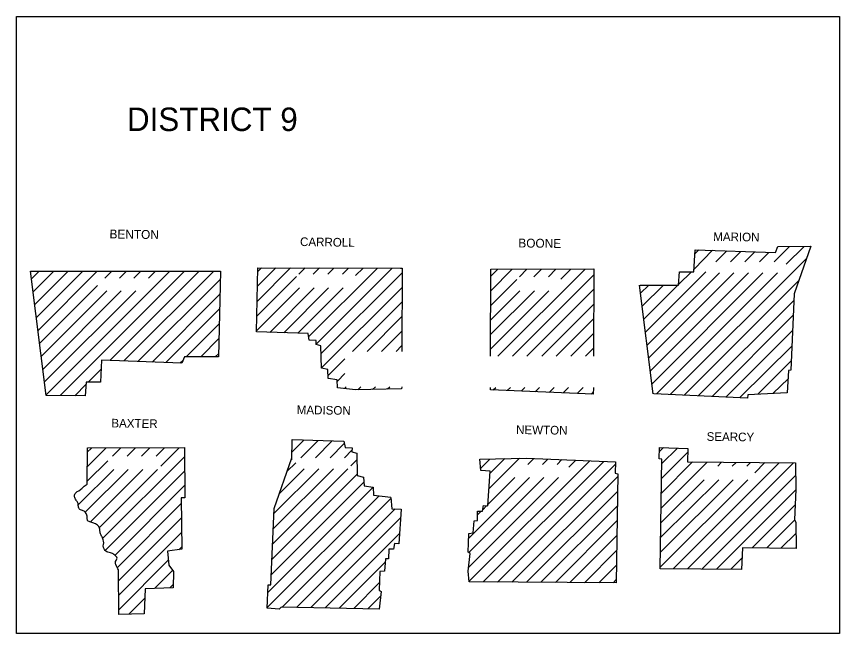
# Model space of a CAD drawing. Extents: x 21307 to 29830, y 1322443 to 1332359.
# Drawn here: x 27385.4 to 27785.4, y 1325389.9 to 1325689.9 of the extents above; entities that cross this region are included whole.
import ezdxf

# ---------------------------------------------------------------- set-up
doc = ezdxf.new("R2010")
doc.units = 0
doc.layers.add('R_Draft', color=7, linetype='Continuous')

msp = doc.modelspace()

# ---------------------------------------------------------------- linework, layer by layer
at = {"layer": 'R_Draft'}
msp.add_lwpolyline([(27385.36, 1325389.92), (27385.36, 1325689.92), (27785.36, 1325689.92), (27785.36, 1325389.92)], close=True, dxfattribs=at)
for points in [[(27688.46, 1325559.32), (27707.16, 1325559.22), (27707.66, 1325565.82), (27714.56, 1325565.82), (27715.16, 1325576.52), (27754.16, 1325575.12), (27755.36, 1325578.12), (27771.46, 1325578.22), (27763.36, 1325555.02), (27761.76, 1325517.92), (27760.56, 1325517.82), (27759.96, 1325506.92)], [(27714.66, 1325567.12), (27723.66, 1325576.22)], [(27715.06, 1325574.52), (27716.96, 1325576.42)], [(27753.56, 1325570.62), (27761.06, 1325578.12)], [(27759.46, 1325569.52), (27768.16, 1325578.12)], [(27703.16, 1325506.22), (27769.36, 1325572.32)], [(27725.26, 1325570.62), (27730.56, 1325575.92)], [(27732.36, 1325570.62), (27737.36, 1325575.72)], [(27739.36, 1325570.62), (27744.26, 1325575.52)], [(27746.46, 1325570.62), (27750.96, 1325575.22)], [(27399.76, 1325505.62), (27392.16, 1325566.12)], [(27392.16, 1325566.12), (27484.46, 1325566.12)], [(27392.66, 1325562.42), (27396.46, 1325566.12)], [(27393.46, 1325556.12), (27403.46, 1325566.12)], [(27394.26, 1325549.92), (27410.46, 1325566.12)], [(27395.06, 1325543.62), (27417.56, 1325566.12)], [(27395.86, 1325537.32), (27424.66, 1325566.12)], [(27399.86, 1325505.92), (27459.96, 1325566.12)], [(27406.66, 1325505.62), (27467.06, 1325566.12)], [(27428.26, 1325562.62), (27431.76, 1325566.12)], [(27430.76, 1325522.62), (27474.16, 1325566.12)], [(27435.36, 1325562.62), (27438.76, 1325566.12)], [(27437.56, 1325522.42), (27481.26, 1325566.12)], [(27442.36, 1325562.62), (27445.86, 1325566.12)], [(27449.46, 1325562.62), (27452.96, 1325566.12)], [(27484.46, 1325566.12), (27483.56, 1325524.52)], [(27501.96, 1325536.52), (27502.66, 1325567.72)], [(27502.26, 1325551.42), (27518.56, 1325567.72)], [(27502.46, 1325558.72), (27511.46, 1325567.72)], [(27502.66, 1325565.92), (27504.46, 1325567.72)], [(27502.66, 1325567.72), (27572.06, 1325567.62), (27572.76, 1325567.62)], [(27522.56, 1325564.62), (27525.66, 1325567.72)], [(27527.36, 1325534.12), (27560.86, 1325567.62)], [(27529.56, 1325564.62), (27532.66, 1325567.72)], [(27530.96, 1325530.62), (27567.96, 1325567.62)], [(27533.46, 1325526.02), (27572.76, 1325565.32)], [(27536.76, 1325564.62), (27539.66, 1325567.62)], [(27543.76, 1325564.62), (27546.76, 1325567.62)], [(27550.16, 1325563.92), (27553.86, 1325567.62)], [(27572.76, 1325567.62), (27572.66, 1325527.02)], [(27615.76, 1325563.52), (27619.26, 1325567.02)], [(27615.76, 1325524.72), (27615.86, 1325567.02)], [(27615.86, 1325567.02), (27665.96, 1325567.22)], [(27615.86, 1325556.52), (27626.26, 1325567.02)], [(27619.36, 1325524.72), (27661.76, 1325567.12)], [(27626.46, 1325524.72), (27665.86, 1325564.12)], [(27629.76, 1325563.32), (27633.46, 1325567.02)], [(27636.76, 1325563.32), (27640.46, 1325567.02)], [(27643.86, 1325563.32), (27647.56, 1325567.02)], [(27649.86, 1325562.22), (27654.76, 1325567.12)], [(27665.96, 1325567.22), (27665.76, 1325524.72)], [(27691.06, 1325536.42), (27720.36, 1325565.72)], [(27691.86, 1325530.12), (27726.96, 1325565.22)], [(27692.66, 1325523.92), (27733.96, 1325565.22)], [(27693.46, 1325517.62), (27741.06, 1325565.22)], [(27694.26, 1325511.32), (27748.16, 1325565.22)], [(27696.46, 1325506.52), (27755.26, 1325565.22)], [(27707.26, 1325559.72), (27713.36, 1325565.82)], [(27444.36, 1325522.22), (27484.36, 1325562.12)], [(27502.16, 1325544.22), (27521.46, 1325563.52)], [(27615.86, 1325549.42), (27628.46, 1325562.02)], [(27709.96, 1325505.92), (27765.56, 1325561.52)], [(27396.66, 1325531.02), (27424.76, 1325559.12)], [(27397.46, 1325524.72), (27429.26, 1325556.52)], [(27398.26, 1325518.52), (27436.26, 1325556.52)], [(27399.06, 1325512.22), (27443.36, 1325556.52)], [(27501.96, 1325537.02), (27522.86, 1325557.92)], [(27508.46, 1325536.32), (27530.06, 1325557.92)], [(27515.26, 1325536.12), (27537.06, 1325557.92)], [(27522.16, 1325535.92), (27544.16, 1325557.92)], [(27533.56, 1325519.02), (27572.76, 1325558.22)], [(27615.76, 1325528.12), (27644.16, 1325556.52)], [(27615.76, 1325535.22), (27637.06, 1325556.52)], [(27615.86, 1325542.42), (27629.96, 1325556.52)], [(27633.46, 1325524.72), (27665.86, 1325557.12)], [(27694.76, 1325506.52), (27688.16, 1325559.32)], [(27688.66, 1325555.32), (27692.76, 1325559.32)], [(27689.46, 1325549.02), (27699.76, 1325559.32)], [(27690.26, 1325542.72), (27706.76, 1325559.32)], [(27451.26, 1325521.92), (27484.16, 1325554.92)], [(27716.66, 1325505.52), (27763.26, 1325552.02)], [(27548.66, 1325527.02), (27572.66, 1325551.02)], [(27640.66, 1325524.72), (27665.86, 1325549.92)], [(27457.96, 1325521.62), (27484.06, 1325547.72)], [(27555.76, 1325527.02), (27572.66, 1325544.02)], [(27723.46, 1325505.22), (27762.86, 1325544.62)], [(27467.86, 1325524.42), (27483.86, 1325540.52)], [(27647.66, 1325524.72), (27665.86, 1325542.92)], [(27572.66, 1325509.92), (27572.56, 1325508.92), (27550.16, 1325508.42), (27541.46, 1325509.32), (27541.26, 1325513.32), (27536.86, 1325513.92), (27536.66, 1325518.22), (27533.56, 1325518.92), (27533.36, 1325529.82), (27530.96, 1325530.42), (27531.06, 1325532.42), (27527.66, 1325532.52), (27527.06, 1325535.72), (27501.96, 1325536.52)], [(27562.76, 1325527.02), (27572.56, 1325536.82)], [(27730.26, 1325504.92), (27762.56, 1325537.32)], [(27474.96, 1325524.42), (27483.76, 1325533.32)], [(27654.76, 1325524.72), (27665.76, 1325535.72)], [(27569.86, 1325527.02), (27572.56, 1325529.82)], [(27661.86, 1325524.72), (27665.76, 1325528.62)], [(27736.96, 1325504.62), (27762.26, 1325529.82)], [(27483.56, 1325524.52), (27466.96, 1325524.42), (27465.76, 1325521.42), (27426.76, 1325522.82), (27426.16, 1325512.12), (27419.26, 1325512.12), (27418.76, 1325505.52), (27399.76, 1325505.62)], [(27481.96, 1325524.42), (27483.66, 1325526.02)], [(27464.76, 1325521.42), (27466.46, 1325523.02)], [(27536.86, 1325515.32), (27544.96, 1325523.42)], [(27745.66, 1325506.22), (27761.86, 1325522.42)], [(27420.16, 1325512.12), (27426.56, 1325518.52)], [(27541.36, 1325512.62), (27544.96, 1325516.32)], [(27753.16, 1325506.72), (27760.36, 1325513.82)], [(27413.66, 1325505.52), (27419.26, 1325511.22)], [(27544.76, 1325509.02), (27545.66, 1325509.92)], [(27551.26, 1325508.42), (27552.76, 1325509.92)], [(27558.46, 1325508.52), (27559.86, 1325509.92)], [(27565.76, 1325508.82), (27566.86, 1325509.92)], [(27615.66, 1325508.32), (27615.76, 1325509.52)], [(27665.66, 1325506.22), (27615.66, 1325508.32)], [(27617.06, 1325508.32), (27618.26, 1325509.52)], [(27623.86, 1325508.02), (27625.46, 1325509.52)], [(27630.66, 1325507.72), (27632.46, 1325509.52)], [(27637.46, 1325507.42), (27639.56, 1325509.52)], [(27644.26, 1325507.12), (27646.66, 1325509.52)], [(27651.06, 1325506.92), (27653.66, 1325509.52)], [(27657.86, 1325506.62), (27660.76, 1325509.52)], [(27665.76, 1325509.52), (27665.66, 1325506.22)], [(27664.66, 1325506.32), (27665.76, 1325507.42)], [(27759.96, 1325506.92), (27740.76, 1325506.02), (27740.56, 1325504.42), (27695.06, 1325506.52)], [(27519.16, 1325474.42), (27519.36, 1325484.32)], [(27519.16, 1325478.12), (27525.16, 1325484.12)], [(27519.36, 1325484.32), (27544.46, 1325483.52), (27545.06, 1325480.32), (27548.46, 1325480.22), (27548.36, 1325478.22), (27550.76, 1325477.62), (27550.96, 1325466.72), (27554.06, 1325466.02), (27554.26, 1325461.72), (27558.66, 1325461.12), (27558.86, 1325457.12), (27567.36, 1325456.22)], [(27419.66, 1325462.62), (27419.86, 1325480.22)], [(27419.76, 1325471.02), (27428.86, 1325480.12)], [(27419.76, 1325478.12), (27421.86, 1325480.12)], [(27419.86, 1325480.22), (27466.96, 1325480.32)], [(27432.06, 1325476.22), (27435.96, 1325480.12)], [(27466.96, 1325480.32), (27467.16, 1325455.92), (27465.46, 1325455.82), (27465.76, 1325430.92), (27458.76, 1325429.92), (27459.36, 1325423.22), (27461.76, 1325420.12), (27461.56, 1325412.22), (27447.96, 1325411.72), (27447.46, 1325399.52), (27435.06, 1325399.12)], [(27439.16, 1325476.22), (27443.06, 1325480.12)], [(27446.16, 1325476.22), (27450.16, 1325480.22)], [(27453.26, 1325476.22), (27457.26, 1325480.22)], [(27455.46, 1325471.32), (27464.36, 1325480.22)], [(27523.56, 1325475.42), (27531.96, 1325483.82)], [(27530.66, 1325475.42), (27538.86, 1325483.62)], [(27537.76, 1325475.42), (27544.66, 1325482.32)], [(27698.26, 1325421.42), (27699.06, 1325474.62), (27697.76, 1325474.92), (27697.86, 1325480.42)], [(27697.86, 1325480.42), (27711.56, 1325479.82), (27711.46, 1325473.32), (27763.96, 1325472.92)], [(27697.86, 1325478.42), (27699.76, 1325480.42)], [(27699.06, 1325472.52), (27706.56, 1325480.02)], [(27544.76, 1325475.42), (27548.36, 1325479.02)], [(27698.96, 1325465.42), (27711.46, 1325477.92)], [(27419.76, 1325463.92), (27429.76, 1325473.92)], [(27427.36, 1325436.22), (27466.96, 1325475.82)], [(27561.66, 1325401.82), (27513.96, 1325402.72), (27513.06, 1325401.82), (27507.16, 1325402.32), (27507.76, 1325413.52), (27508.96, 1325413.62), (27510.56, 1325450.72), (27519.16, 1325475.42)], [(27516.76, 1325468.62), (27521.06, 1325472.92)], [(27547.86, 1325471.52), (27550.76, 1325474.42)], [(27604.86, 1325420.32), (27605.86, 1325428.82), (27604.86, 1325429.52), (27605.16, 1325438.52), (27607.36, 1325438.82), (27607.86, 1325444.72), (27609.36, 1325444.82), (27609.46, 1325449.42), (27611.86, 1325449.42), (27612.26, 1325452.12), (27614.36, 1325452.02), (27615.56, 1325468.82), (27610.96, 1325469.12), (27610.56, 1325474.72)], [(27605.36, 1325415.32), (27664.06, 1325473.92)], [(27610.56, 1325474.72), (27610.76, 1325474.72), (27633.16, 1325475.22)], [(27610.96, 1325470.32), (27615.36, 1325474.72)], [(27612.16, 1325415.02), (27670.86, 1325473.62)], [(27614.96, 1325460.22), (27629.86, 1325475.12)], [(27615.46, 1325467.72), (27622.66, 1325475.02)], [(27619.16, 1325414.92), (27676.36, 1325472.12)], [(27633.16, 1325475.22), (27676.46, 1325473.42)], [(27633.96, 1325472.12), (27636.86, 1325475.02)], [(27641.06, 1325472.12), (27643.66, 1325474.72)], [(27648.06, 1325472.12), (27650.46, 1325474.52)], [(27653.86, 1325470.82), (27657.26, 1325474.22)], [(27676.46, 1325473.42), (27676.36, 1325467.92), (27677.66, 1325467.62), (27676.86, 1325414.52)], [(27698.76, 1325451.02), (27720.96, 1325473.22)], [(27698.86, 1325458.22), (27713.96, 1325473.32)], [(27704.46, 1325421.42), (27756.06, 1325472.92)], [(27711.46, 1325421.32), (27763.06, 1325472.92)], [(27726.16, 1325471.32), (27728.06, 1325473.22)], [(27733.26, 1325471.32), (27735.06, 1325473.12)], [(27740.26, 1325471.32), (27742.06, 1325473.12)], [(27744.16, 1325468.12), (27749.06, 1325473.02)], [(27763.96, 1325472.92), (27764.06, 1325460.02)], [(27415.36, 1325452.52), (27432.66, 1325469.72)], [(27418.96, 1325449.02), (27439.66, 1325469.72)], [(27421.16, 1325444.12), (27446.76, 1325469.72)], [(27425.66, 1325441.52), (27453.86, 1325469.72)], [(27428.66, 1325430.42), (27467.06, 1325468.82)], [(27509.86, 1325433.42), (27546.46, 1325470.02)], [(27510.16, 1325440.82), (27539.36, 1325470.02)], [(27510.46, 1325448.22), (27532.36, 1325470.02)], [(27513.06, 1325457.92), (27525.26, 1325470.02)], [(27509.56, 1325426.12), (27550.86, 1325467.42)], [(27605.16, 1325422.12), (27648.76, 1325465.72)], [(27605.16, 1325436.22), (27634.66, 1325465.72)], [(27605.26, 1325429.32), (27641.66, 1325465.72)], [(27614.46, 1325452.62), (27627.56, 1325465.72)], [(27626.16, 1325414.82), (27677.56, 1325466.32)], [(27698.36, 1325422.32), (27740.76, 1325464.72)], [(27698.36, 1325429.42), (27733.66, 1325464.72)], [(27698.56, 1325436.72), (27726.66, 1325464.72)], [(27698.56, 1325443.82), (27719.56, 1325464.72)], [(27718.46, 1325421.22), (27763.96, 1325466.72)], [(27433.26, 1325428.02), (27467.06, 1325461.82)], [(27507.56, 1325409.92), (27558.66, 1325461.02)], [(27509.26, 1325418.62), (27554.16, 1325463.52)], [(27764.06, 1325460.02), (27763.46, 1325445.22), (27764.16, 1325444.02), (27764.36, 1325431.32)], [(27507.26, 1325402.52), (27561.46, 1325456.72)], [(27567.36, 1325456.02), (27567.76, 1325450.62), (27572.36, 1325450.32), (27571.16, 1325433.52), (27569.06, 1325433.62), (27568.66, 1325430.92), (27566.26, 1325430.92), (27566.16, 1325426.32), (27564.66, 1325426.22), (27564.16, 1325420.32), (27561.96, 1325420.02), (27561.66, 1325411.02), (27562.66, 1325410.32), (27561.66, 1325401.82)], [(27633.26, 1325414.82), (27677.56, 1325459.12)], [(27725.56, 1325421.22), (27763.96, 1325459.62)], [(27434.46, 1325422.02), (27465.46, 1325453.12)], [(27514.56, 1325402.72), (27567.36, 1325455.52)], [(27611.96, 1325450.12), (27613.86, 1325452.02)], [(27742.96, 1325431.62), (27763.76, 1325452.42)], [(27521.46, 1325402.62), (27569.36, 1325450.52)], [(27609.46, 1325447.62), (27611.26, 1325449.42)], [(27640.26, 1325414.82), (27677.36, 1325451.92)], [(27434.96, 1325415.52), (27465.56, 1325446.12)], [(27528.46, 1325402.52), (27571.96, 1325446.12)], [(27647.26, 1325414.72), (27677.36, 1325444.82)], [(27749.96, 1325431.52), (27763.56, 1325445.12)], [(27435.06, 1325408.52), (27465.56, 1325439.12)], [(27535.36, 1325402.42), (27571.46, 1325438.52)], [(27654.36, 1325414.72), (27677.16, 1325437.52)], [(27756.86, 1325431.42), (27764.26, 1325438.72)], [(27464.26, 1325430.62), (27465.66, 1325432.12)], [(27661.36, 1325414.62), (27677.16, 1325430.42)], [(27764.36, 1325431.32), (27738.26, 1325431.62), (27737.76, 1325421.12), (27698.26, 1325421.42)], [(27763.96, 1325431.42), (27764.26, 1325431.72)], [(27435.06, 1325401.42), (27459.06, 1325425.52)], [(27542.26, 1325402.22), (27564.46, 1325424.42)], [(27732.56, 1325421.22), (27738.06, 1325426.72)], [(27435.06, 1325399.12), (27434.96, 1325420.82)], [(27452.56, 1325411.92), (27461.26, 1325420.62)], [(27605.36, 1325415.02), (27604.86, 1325420.32)], [(27668.36, 1325414.62), (27676.96, 1325423.22)], [(27675.36, 1325414.52), (27676.86, 1325416.12)], [(27459.96, 1325412.22), (27461.56, 1325413.82)], [(27549.26, 1325402.12), (27561.86, 1325414.72)], [(27676.86, 1325414.52), (27605.36, 1325415.02)], [(27556.16, 1325401.92), (27562.46, 1325408.22)], [(27439.96, 1325399.32), (27447.76, 1325407.12)], [(27447.26, 1325399.52), (27447.46, 1325399.72)]]:
    msp.add_lwpolyline(points, dxfattribs=at)
msp.add_spline([(27434.96, 1325420.82), (27433.66, 1325423.42), (27433.56, 1325424.92), (27434.26, 1325426.62), (27433.16, 1325428.02), (27431.56, 1325429.02), (27429.26, 1325429.72), (27427.96, 1325431.12), (27427.56, 1325432.52), (27427.76, 1325434.02), (27427.56, 1325435.52), (27426.76, 1325437.32), (27426.06, 1325438.82), (27425.86, 1325440.72), (27425.06, 1325442.22), (27423.36, 1325443.42), (27421.56, 1325444.02), (27419.96, 1325444.82), (27419.76, 1325446.52), (27419.26, 1325448.32), (27417.86, 1325449.62), (27416.16, 1325450.22), (27415.46, 1325451.72), (27415.16, 1325453.52), (27414.36, 1325454.82), (27413.56, 1325456.42), (27413.86, 1325458.02), (27416.26, 1325459.72), (27417.86, 1325461.12), (27419.66, 1325462.62)], degree=3, dxfattribs=at)

# ---------------------------------------------------------------- texts
msp.add_text('DISTRICT 9', height=11.4, dxfattribs=at).set_placement((27439.06, 1325634.22))
for s, height, rotation, p in [('BENTON', 4.301, 359.2527, (27430.56, 1325582.02)), ('MARION', 4.201, 359.1854, (27723.96, 1325580.82)), ('CARROLL', 4.201, 359.1481, (27523.16, 1325578.32)), ('BOONE', 4.301, 359.4001, (27629.26, 1325577.62)), ('MADISON', 4.201, 359.0906, (27521.56, 1325496.62)), ('BAXTER', 4.201, 359.2559, (27431.46, 1325490.12)), ('NEWTON', 4.201, 359.2717, (27628.16, 1325486.92)), ('SEARCY', 4.199, 359.2527, (27720.76, 1325483.62))]:
    msp.add_text(s, height=height, rotation=rotation, dxfattribs=at).set_placement(p)

doc.saveas('drawing.dxf')
